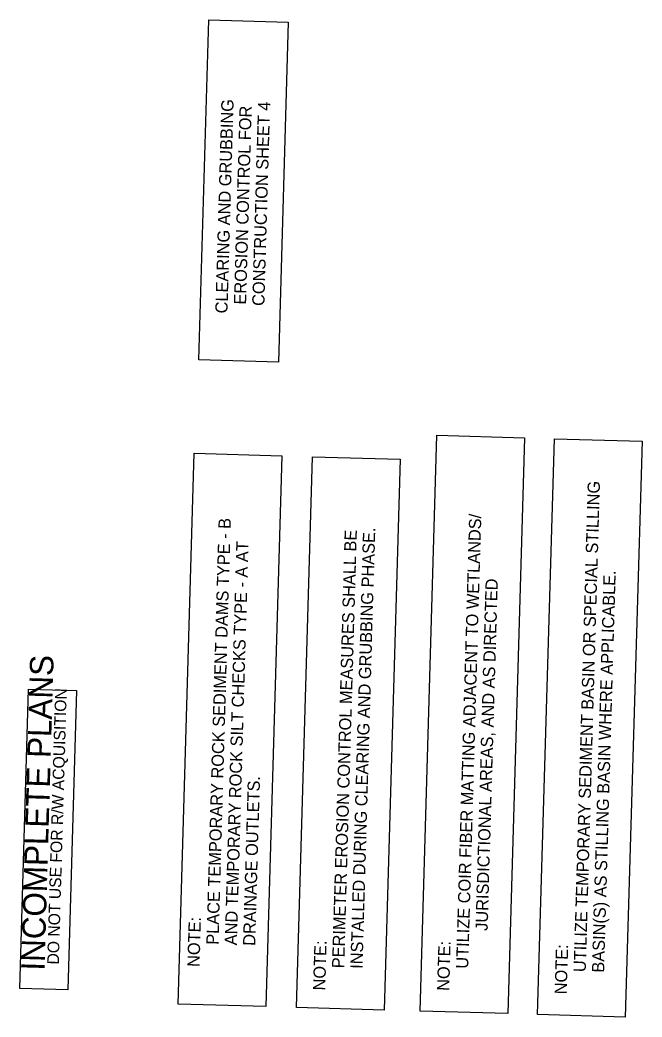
# Model space of a CAD drawing. Extents: x 2096987 to 2098130, y 681809 to 686842.
# Drawn here: x 2097701.9 to 2098007.3, y 681809.1 to 682298.5 of the extents above; entities that cross this region are included whole.
import ezdxf

# ---------------------------------------------------------------- set-up
doc = ezdxf.new("R2010")
doc.units = 0
for name, color, linetype in [('Construction Sheet Number Note CG CELL', 7, 'Continuous'), ('Sediment Dams and Silt Check Note CG CELL', 7, 'Continuous'), ('Sheet Sticker Incomplete CELL', 7, 'Continuous')]:
    doc.layers.add(name, color=color, linetype=linetype)

# ---------------------------------------------------------------- blocks, each defined once
blk = doc.blocks.new('CGNT2')
at = {"layer": 'Sediment Dams and Silt Check Note CG CELL'}
blk.add_lwpolyline([(-2.704, 0.431), (2.704, 0.43125), (2.704, -0.43), (-2.704, -0.43)], close=True, dxfattribs=at)
for s, p in [('NOTE:', (-2.335, 0.231)), ('     PLACE TEMPORARY ROCK SEDIMENT DAMS TYPE - B', (-2.335, 0.05125)), ('     AND TEMPORARY ROCK SILT CHECKS TYPE - A AT', (-2.335, -0.129)), ('     DRAINAGE OUTLETS.', (-2.335, -0.309))]:
    blk.add_text(s, height=0.12, dxfattribs=at).set_placement(p)

msp = doc.modelspace()

# ---------------------------------------------------------------- linework, layer by layer
at = {"layer": 'Construction Sheet Number Note CG CELL'}
for points in [[(2097898.34, 681812.02), (2097906.55, 682094.59), (2097949.58, 682093.34), (2097941.37, 681810.77)], [(2097956.04, 681810.34), (2097964.25, 682092.91), (2098007.28, 682091.66), (2097999.07, 681809.09)]]:
    msp.add_lwpolyline(points, close=True, dxfattribs=at)
at = {"layer": 'Sediment Dams and Silt Check Note CG CELL'}
for points in [[(2097789.81, 682131.63), (2097794.67, 682298.45), (2097833.66, 682297.32), (2097828.81, 682130.49)], [(2097837.72, 681813.78), (2097845.58, 682084.06), (2097888.61, 682082.81), (2097880.76, 681812.53)]]:
    msp.add_lwpolyline(points, close=True, dxfattribs=at)
at = {"layer": 'Sheet Sticker Incomplete CELL'}
msp.add_lwpolyline([(2097725.44, 681822.46), (2097701.95, 681823.14), (2097706.22, 681970.08), (2097729.71, 681969.39)], close=True, dxfattribs=at)

# ---------------------------------------------------------------- block references
at = {"layer": 'Sediment Dams and Silt Check Note CG CELL', "xscale": 50.00000000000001, "yscale": 49.99999999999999, "rotation": 88.33482999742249}
msp.add_blockref('CGNT2', (2097805.02, 681949.99), dxfattribs=at)

# ---------------------------------------------------------------- texts
at = {"layer": 'Construction Sheet Number Note CG CELL'}
for s, p in [('     UTILIZE TEMPORARY SEDIMENT BASIN OR SPECIAL STILLING', (2097979.32, 681819.92)), ('     UTILIZE COIR FIBER MATTING ADJACENT TO WETLANDS/', (2097921.62, 681821.6)), ('     BASIN(S) AS STILLING BASIN WHERE APPLICABLE.', (2097988.32, 681819.67)), ('JURISDICTIONAL AREAS, AND AS DIRECTED', (2097931.49, 681851.33)), ('NOTE:  ', (2097912.63, 681821.87)), ('NOTE:  ', (2097970.33, 681820.19))]:
    msp.add_text(s, height=6, rotation=88.3348, dxfattribs=at).set_placement(p)
at = {"layer": 'Sediment Dams and Silt Check Note CG CELL'}
for s, p in [('CLEARING AND GRUBBING', (2097803.79, 682154.36)), ('EROSION CONTROL FOR', (2097812.92, 682158.69)), ('CONSTRUCTION SHEET 4', (2097821.9, 682158.03)), ('     PERIMETER EROSION CONTROL MEASURES SHALL BE', (2097860.76, 681821.81)), ('     INSTALLED DURING CLEARING AND GRUBBING PHASE.', (2097869.76, 681821.55)), ('NOTE:', (2097851.77, 681822.07))]:
    msp.add_text(s, height=6, rotation=88.3348, dxfattribs=at).set_placement(p)
at = {"layer": 'Sheet Sticker Incomplete CELL'}
for s, height, p in [('INCOMPLETE PLANS', 11.52, (2097714, 681831.74)), ('DO NOT USE FOR R/W ACQUISITION', 5.76, (2097721.04, 681834.79))]:
    msp.add_text(s, height=height, rotation=88.3348, dxfattribs=at).set_placement(p)

doc.saveas('drawing.dxf')
